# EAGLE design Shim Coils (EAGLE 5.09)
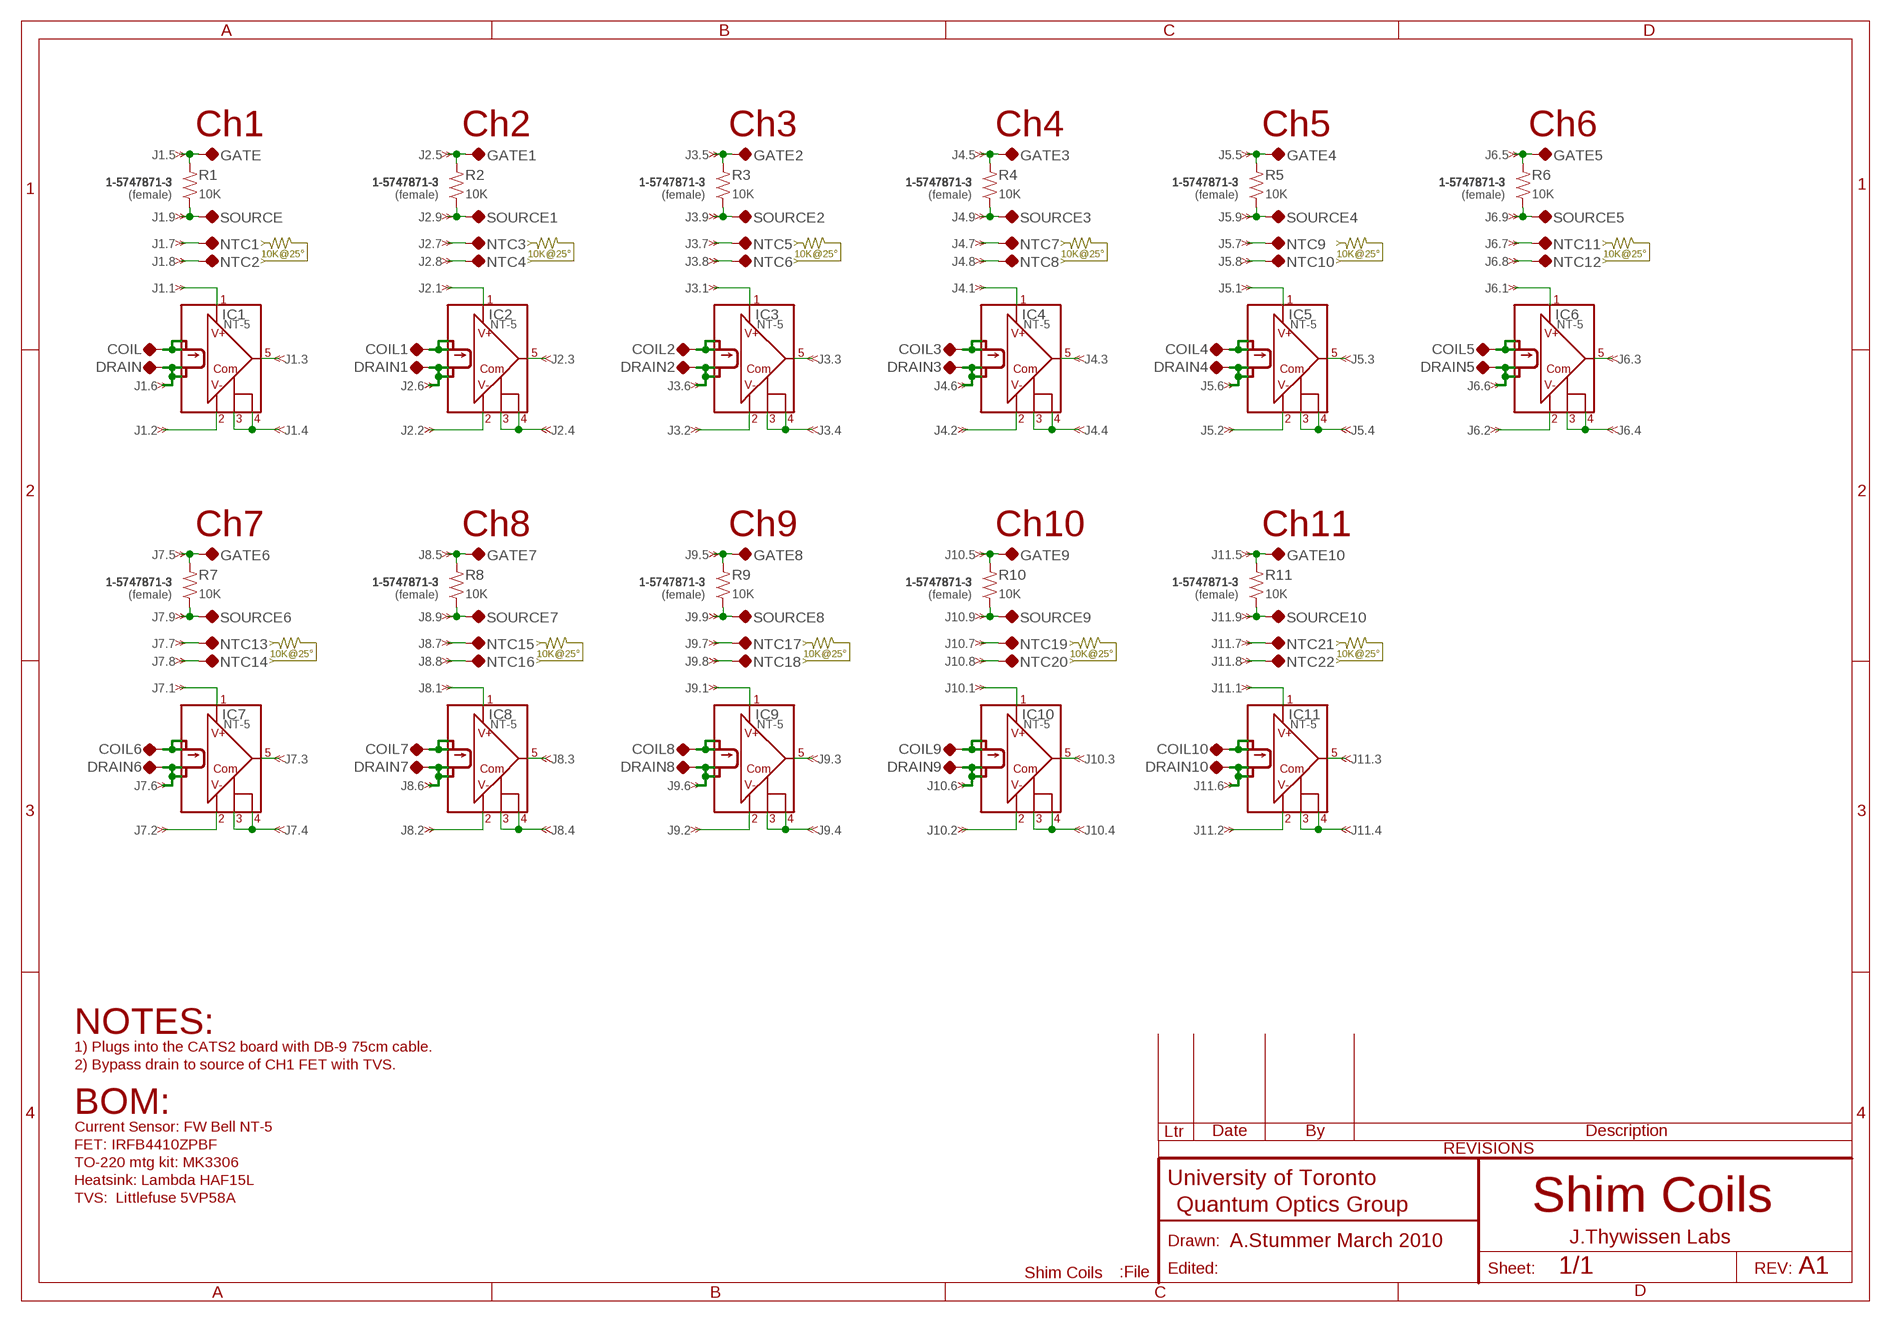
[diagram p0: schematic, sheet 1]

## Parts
COIL  TP-0.052"  [TP-0.052]
COIL1  TP-0.052"  [TP-0.052]
COIL2  TP-0.052"  [TP-0.052]
COIL3  TP-0.052"  [TP-0.052]
COIL4  TP-0.052"  [TP-0.052]
COIL5  TP-0.052"  [TP-0.052]
COIL6  TP-0.052"  [TP-0.052]
COIL7  TP-0.052"  [TP-0.052]
COIL8  TP-0.052"  [TP-0.052]
COIL9  TP-0.052"  [TP-0.052]
COIL10  TP-0.052"  [TP-0.052]
DRAIN  TP-0.052"  [TP-0.052]
DRAIN1  TP-0.052"  [TP-0.052]
DRAIN2  TP-0.052"  [TP-0.052]
DRAIN3  TP-0.052"  [TP-0.052]
DRAIN4  TP-0.052"  [TP-0.052]
DRAIN5  TP-0.052"  [TP-0.052]
DRAIN6  TP-0.052"  [TP-0.052]
DRAIN7  TP-0.052"  [TP-0.052]
DRAIN8  TP-0.052"  [TP-0.052]
DRAIN9  TP-0.052"  [TP-0.052]
DRAIN10  TP-0.052"  [TP-0.052]
GATE  TP-0.052"  [TP-0.052]
GATE1  TP-0.052"  [TP-0.052]
GATE2  TP-0.052"  [TP-0.052]
GATE3  TP-0.052"  [TP-0.052]
GATE4  TP-0.052"  [TP-0.052]
GATE5  TP-0.052"  [TP-0.052]
GATE6  TP-0.052"  [TP-0.052]
GATE7  TP-0.052"  [TP-0.052]
GATE8  TP-0.052"  [TP-0.052]
GATE9  TP-0.052"  [TP-0.052]
GATE10  TP-0.052"  [TP-0.052]
IC1  NT-5  CURRENT_SENSOR:NT-X(F.W.BELL)-NT5/15/25  [CURRENT_SENSOR:NT-5/15/25(F.W.BELL)]
IC2  NT-5  CURRENT_SENSOR:NT-X(F.W.BELL)-NT5/15/25  [CURRENT_SENSOR:NT-5/15/25(F.W.BELL)]
IC3  NT-5  CURRENT_SENSOR:NT-X(F.W.BELL)-NT5/15/25  [CURRENT_SENSOR:NT-5/15/25(F.W.BELL)]
IC4  NT-5  CURRENT_SENSOR:NT-X(F.W.BELL)-NT5/15/25  [CURRENT_SENSOR:NT-5/15/25(F.W.BELL)]
IC5  NT-5  CURRENT_SENSOR:NT-X(F.W.BELL)-NT5/15/25  [CURRENT_SENSOR:NT-5/15/25(F.W.BELL)]
IC6  NT-5  CURRENT_SENSOR:NT-X(F.W.BELL)-NT5/15/25  [CURRENT_SENSOR:NT-5/15/25(F.W.BELL)]
IC7  NT-5  CURRENT_SENSOR:NT-X(F.W.BELL)-NT5/15/25  [CURRENT_SENSOR:NT-5/15/25(F.W.BELL)]
IC8  NT-5  CURRENT_SENSOR:NT-X(F.W.BELL)-NT5/15/25  [CURRENT_SENSOR:NT-5/15/25(F.W.BELL)]
IC9  NT-5  CURRENT_SENSOR:NT-X(F.W.BELL)-NT5/15/25  [CURRENT_SENSOR:NT-5/15/25(F.W.BELL)]
IC10  NT-5  CURRENT_SENSOR:NT-X(F.W.BELL)-NT5/15/25  [CURRENT_SENSOR:NT-5/15/25(F.W.BELL)]
IC11  NT-5  CURRENT_SENSOR:NT-X(F.W.BELL)-NT5/15/25  [CURRENT_SENSOR:NT-5/15/25(F.W.BELL)]
J1  1-5747871-3  CONN-DB9-TYPE2-TYCO_5747150-7_ET_AL  [CONN-DB9-MALE-V2]
J2  1-5747871-3  CONN-DB9-TYPE2-TYCO_5747150-7_ET_AL  [CONN-DB9-MALE-V2]
J3  1-5747871-3  CONN-DB9-TYPE2-TYCO_5747150-7_ET_AL  [CONN-DB9-MALE-V2]
J4  1-5747871-3  CONN-DB9-TYPE2-TYCO_5747150-7_ET_AL  [CONN-DB9-MALE-V2]
J5  1-5747871-3  CONN-DB9-TYPE2-TYCO_5747150-7_ET_AL  [CONN-DB9-MALE-V2]
J6  1-5747871-3  CONN-DB9-TYPE2-TYCO_5747150-7_ET_AL  [CONN-DB9-MALE-V2]
J7  1-5747871-3  CONN-DB9-TYPE2-TYCO_5747150-7_ET_AL  [CONN-DB9-MALE-V2]
J8  1-5747871-3  CONN-DB9-TYPE2-TYCO_5747150-7_ET_AL  [CONN-DB9-MALE-V2]
J9  1-5747871-3  CONN-DB9-TYPE2-TYCO_5747150-7_ET_AL  [CONN-DB9-MALE-V2]
J10  1-5747871-3  CONN-DB9-TYPE2-TYCO_5747150-7_ET_AL  [CONN-DB9-MALE-V2]
J11  1-5747871-3  CONN-DB9-TYPE2-TYCO_5747150-7_ET_AL  [CONN-DB9-MALE-V2]
NTC1  TP-0.052"  [TP-0.052]
NTC2  TP-0.052"  [TP-0.052]
NTC3  TP-0.052"  [TP-0.052]
NTC4  TP-0.052"  [TP-0.052]
NTC5  TP-0.052"  [TP-0.052]
NTC6  TP-0.052"  [TP-0.052]
NTC7  TP-0.052"  [TP-0.052]
NTC8  TP-0.052"  [TP-0.052]
NTC9  TP-0.052"  [TP-0.052]
NTC10  TP-0.052"  [TP-0.052]
NTC11  TP-0.052"  [TP-0.052]
NTC12  TP-0.052"  [TP-0.052]
NTC13  TP-0.052"  [TP-0.052]
NTC14  TP-0.052"  [TP-0.052]
NTC15  TP-0.052"  [TP-0.052]
NTC16  TP-0.052"  [TP-0.052]
NTC17  TP-0.052"  [TP-0.052]
NTC18  TP-0.052"  [TP-0.052]
NTC19  TP-0.052"  [TP-0.052]
NTC20  TP-0.052"  [TP-0.052]
NTC21  TP-0.052"  [TP-0.052]
NTC22  TP-0.052"  [TP-0.052]
R1  10K  R-V-0805  [2012(0805)]
R2  10K  R-V-0805  [2012(0805)]
R3  10K  R-V-0805  [2012(0805)]
R4  10K  R-V-0805  [2012(0805)]
R5  10K  R-V-0805  [2012(0805)]
R6  10K  R-V-0805  [2012(0805)]
R7  10K  R-V-0805  [2012(0805)]
R8  10K  R-V-0805  [2012(0805)]
R9  10K  R-V-0805  [2012(0805)]
R10  10K  R-V-0805  [2012(0805)]
R11  10K  R-V-0805  [2012(0805)]
SOURCE  TP-0.052"  [TP-0.052]
SOURCE1  TP-0.052"  [TP-0.052]
SOURCE2  TP-0.052"  [TP-0.052]
SOURCE3  TP-0.052"  [TP-0.052]
SOURCE4  TP-0.052"  [TP-0.052]
SOURCE5  TP-0.052"  [TP-0.052]
SOURCE6  TP-0.052"  [TP-0.052]
SOURCE7  TP-0.052"  [TP-0.052]
SOURCE8  TP-0.052"  [TP-0.052]
SOURCE9  TP-0.052"  [TP-0.052]
SOURCE10  TP-0.052"  [TP-0.052]

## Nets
N$1: IC1.+V(+VS) J1.5
N$2: IC1.-V(-VS) J1.4
N$3: IC1.OUT J1.3
N$4: IC1.GND1(COM1) IC1.GND2(COM2) J1.2
N$5: GATE.TP J1.1 R1.2
N$6: DRAIN.TP IC1.CURRENT-1 IC1.CURRENT-2 J1.9
N$7: J1.8 NTC1.TP
N$8: J1.7 NTC2.TP
N$9: J1.6 R1.1 SOURCE.TP
N$10: COIL.TP IC1.CURRENT+1 IC1.CURRENT+2
N$11: IC2.+V(+VS) J2.5
N$12: IC2.-V(-VS) J2.4
N$13: IC2.OUT J2.3
N$14: IC2.GND1(COM1) IC2.GND2(COM2) J2.2
N$15: GATE1.TP J2.1 R2.2
N$16: J2.8 NTC3.TP
N$17: J2.7 NTC4.TP
N$18: J2.6 R2.1 SOURCE1.TP
N$19: DRAIN1.TP IC2.CURRENT-1 IC2.CURRENT-2 J2.9
N$20: COIL1.TP IC2.CURRENT+1 IC2.CURRENT+2
N$21: IC3.+V(+VS) J3.5
N$22: IC3.-V(-VS) J3.4
N$23: IC3.OUT J3.3
N$24: IC3.GND1(COM1) IC3.GND2(COM2) J3.2
N$25: GATE2.TP J3.1 R3.2
N$26: J3.8 NTC5.TP
N$27: J3.7 NTC6.TP
N$28: J3.6 R3.1 SOURCE2.TP
N$29: DRAIN2.TP IC3.CURRENT-1 IC3.CURRENT-2 J3.9
N$30: COIL2.TP IC3.CURRENT+1 IC3.CURRENT+2
N$31: IC4.+V(+VS) J4.5
N$32: IC4.-V(-VS) J4.4
N$33: IC4.OUT J4.3
N$34: IC4.GND1(COM1) IC4.GND2(COM2) J4.2
N$35: GATE3.TP J4.1 R4.2
N$36: J4.8 NTC7.TP
N$37: J4.7 NTC8.TP
N$38: J4.6 R4.1 SOURCE3.TP
N$39: DRAIN3.TP IC4.CURRENT-1 IC4.CURRENT-2 J4.9
N$40: COIL3.TP IC4.CURRENT+1 IC4.CURRENT+2
N$41: IC5.+V(+VS) J5.5
N$42: IC5.-V(-VS) J5.4
N$43: IC5.OUT J5.3
N$44: IC5.GND1(COM1) IC5.GND2(COM2) J5.2
N$45: GATE4.TP J5.1 R5.2
N$46: J5.8 NTC9.TP
N$47: J5.7 NTC10.TP
N$48: J5.6 R5.1 SOURCE4.TP
N$49: DRAIN4.TP IC5.CURRENT-1 IC5.CURRENT-2 J5.9
N$50: COIL4.TP IC5.CURRENT+1 IC5.CURRENT+2
N$51: IC6.+V(+VS) J6.5
N$52: IC6.-V(-VS) J6.4
N$53: IC6.OUT J6.3
N$54: IC6.GND1(COM1) IC6.GND2(COM2) J6.2
N$55: GATE5.TP J6.1 R6.2
N$56: J6.8 NTC11.TP
N$57: J6.7 NTC12.TP
N$58: J6.6 R6.1 SOURCE5.TP
N$59: DRAIN5.TP IC6.CURRENT-1 IC6.CURRENT-2 J6.9
N$60: COIL5.TP IC6.CURRENT+1 IC6.CURRENT+2
N$61: IC7.+V(+VS) J7.5
N$62: IC7.-V(-VS) J7.4
N$63: IC7.OUT J7.3
N$64: IC7.GND1(COM1) IC7.GND2(COM2) J7.2
N$65: GATE6.TP J7.1 R7.2
N$66: J7.8 NTC13.TP
N$67: J7.7 NTC14.TP
N$68: J7.6 R7.1 SOURCE6.TP
N$69: DRAIN6.TP IC7.CURRENT-1 IC7.CURRENT-2 J7.9
N$70: COIL6.TP IC7.CURRENT+1 IC7.CURRENT+2
N$71: IC8.+V(+VS) J8.5
N$72: IC8.-V(-VS) J8.4
N$73: IC8.OUT J8.3
N$74: IC8.GND1(COM1) IC8.GND2(COM2) J8.2
N$75: GATE7.TP J8.1 R8.2
N$76: J8.8 NTC15.TP
N$77: J8.7 NTC16.TP
N$78: J8.6 R8.1 SOURCE7.TP
N$79: DRAIN7.TP IC8.CURRENT-1 IC8.CURRENT-2 J8.9
N$80: COIL7.TP IC8.CURRENT+1 IC8.CURRENT+2
N$81: IC9.+V(+VS) J9.5
N$82: IC9.-V(-VS) J9.4
N$83: IC9.OUT J9.3
N$84: IC9.GND1(COM1) IC9.GND2(COM2) J9.2
N$85: GATE8.TP J9.1 R9.2
N$86: J9.8 NTC17.TP
N$87: J9.7 NTC18.TP
N$88: J9.6 R9.1 SOURCE8.TP
N$89: DRAIN8.TP IC9.CURRENT-1 IC9.CURRENT-2 J9.9
N$90: COIL8.TP IC9.CURRENT+1 IC9.CURRENT+2
N$91: IC10.+V(+VS) J10.5
N$92: IC10.-V(-VS) J10.4
N$93: IC10.OUT J10.3
N$94: IC10.GND1(COM1) IC10.GND2(COM2) J10.2
N$95: GATE9.TP J10.1 R10.2
N$96: J10.8 NTC19.TP
N$97: J10.7 NTC20.TP
N$98: J10.6 R10.1 SOURCE9.TP
N$99: DRAIN9.TP IC10.CURRENT-1 IC10.CURRENT-2 J10.9
N$100: COIL9.TP IC10.CURRENT+1 IC10.CURRENT+2
N$101: IC11.+V(+VS) J11.5
N$102: IC11.-V(-VS) J11.4
N$103: IC11.OUT J11.3
N$104: IC11.GND1(COM1) IC11.GND2(COM2) J11.2
N$105: GATE10.TP J11.1 R11.2
N$106: J11.8 NTC21.TP
N$107: J11.7 NTC22.TP
N$108: J11.6 R11.1 SOURCE10.TP
N$109: DRAIN10.TP IC11.CURRENT-1 IC11.CURRENT-2 J11.9
N$110: COIL10.TP IC11.CURRENT+1 IC11.CURRENT+2

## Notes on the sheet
- Ch1 | Ch2 | Ch3 | Ch4 | Ch5 | Ch6
- (female) | (female) | (female) | (female) | (female) | (female)
- 10K@25° | 10K@25° | 10K@25° | 10K@25° | 10K@25° | 10K@25°
- Ch7 | Ch8 | Ch9 | Ch10 | Ch11
- (female) | (female) | (female) | (female) | (female)
- 10K@25° | 10K@25° | 10K@25° | 10K@25° | 10K@25°
- NOTES:
- 1) Plugs into the CATS2 board with DB-9 75cm cable.
- 2) Bypass drain to source of CH1 FET with TVS.
- BOM:
- Current Sensor: FW Bell NT-5
- FET: IRFB4410ZPBF
- TO-220 mtg kit: MK3306
- Heatsink: Lambda HAF15L
- TVS:  Littlefuse 5VP58A
- Shim Coils
- A.Stummer March 2010 | J.Thywissen Labs
- A1

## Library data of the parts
COIL COIL1-COIL10 DRAIN DRAIN1-DRAIN10 GATE GATE1-GATE10 NTC1-NTC22 SOURCE SOURCE1-SOURCE10 = QuantumOptics:TP: Testpoint, either SMT pad, small hole or loop style TP such as Keystone 5002K (0.042").
IC1-IC11 = QuantumOptics:CURRENT_SENSOR:NT-X(F.W.BELL): Current Sensor, NT-5 -15 -25, F.W.Bell, 5/15/25A, bipolar, ±15V supply. http://www.sypris.com/filemanager/library/NT-Datasheet.pdf
J1-J11 = QuantumOptics:CONN-DB9-TYPE2: Connector, DB9, board mount, e.g. Tyco 1-5747150-4.
R1-R11 = QuantumOptics:R-V-*: Resistor, SMT & Through-Hole, vertical symbol

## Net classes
0 default: width 0.2 mm, drill 0.508 mm
1 Power: width 1.27 mm, drill 0.711 mm

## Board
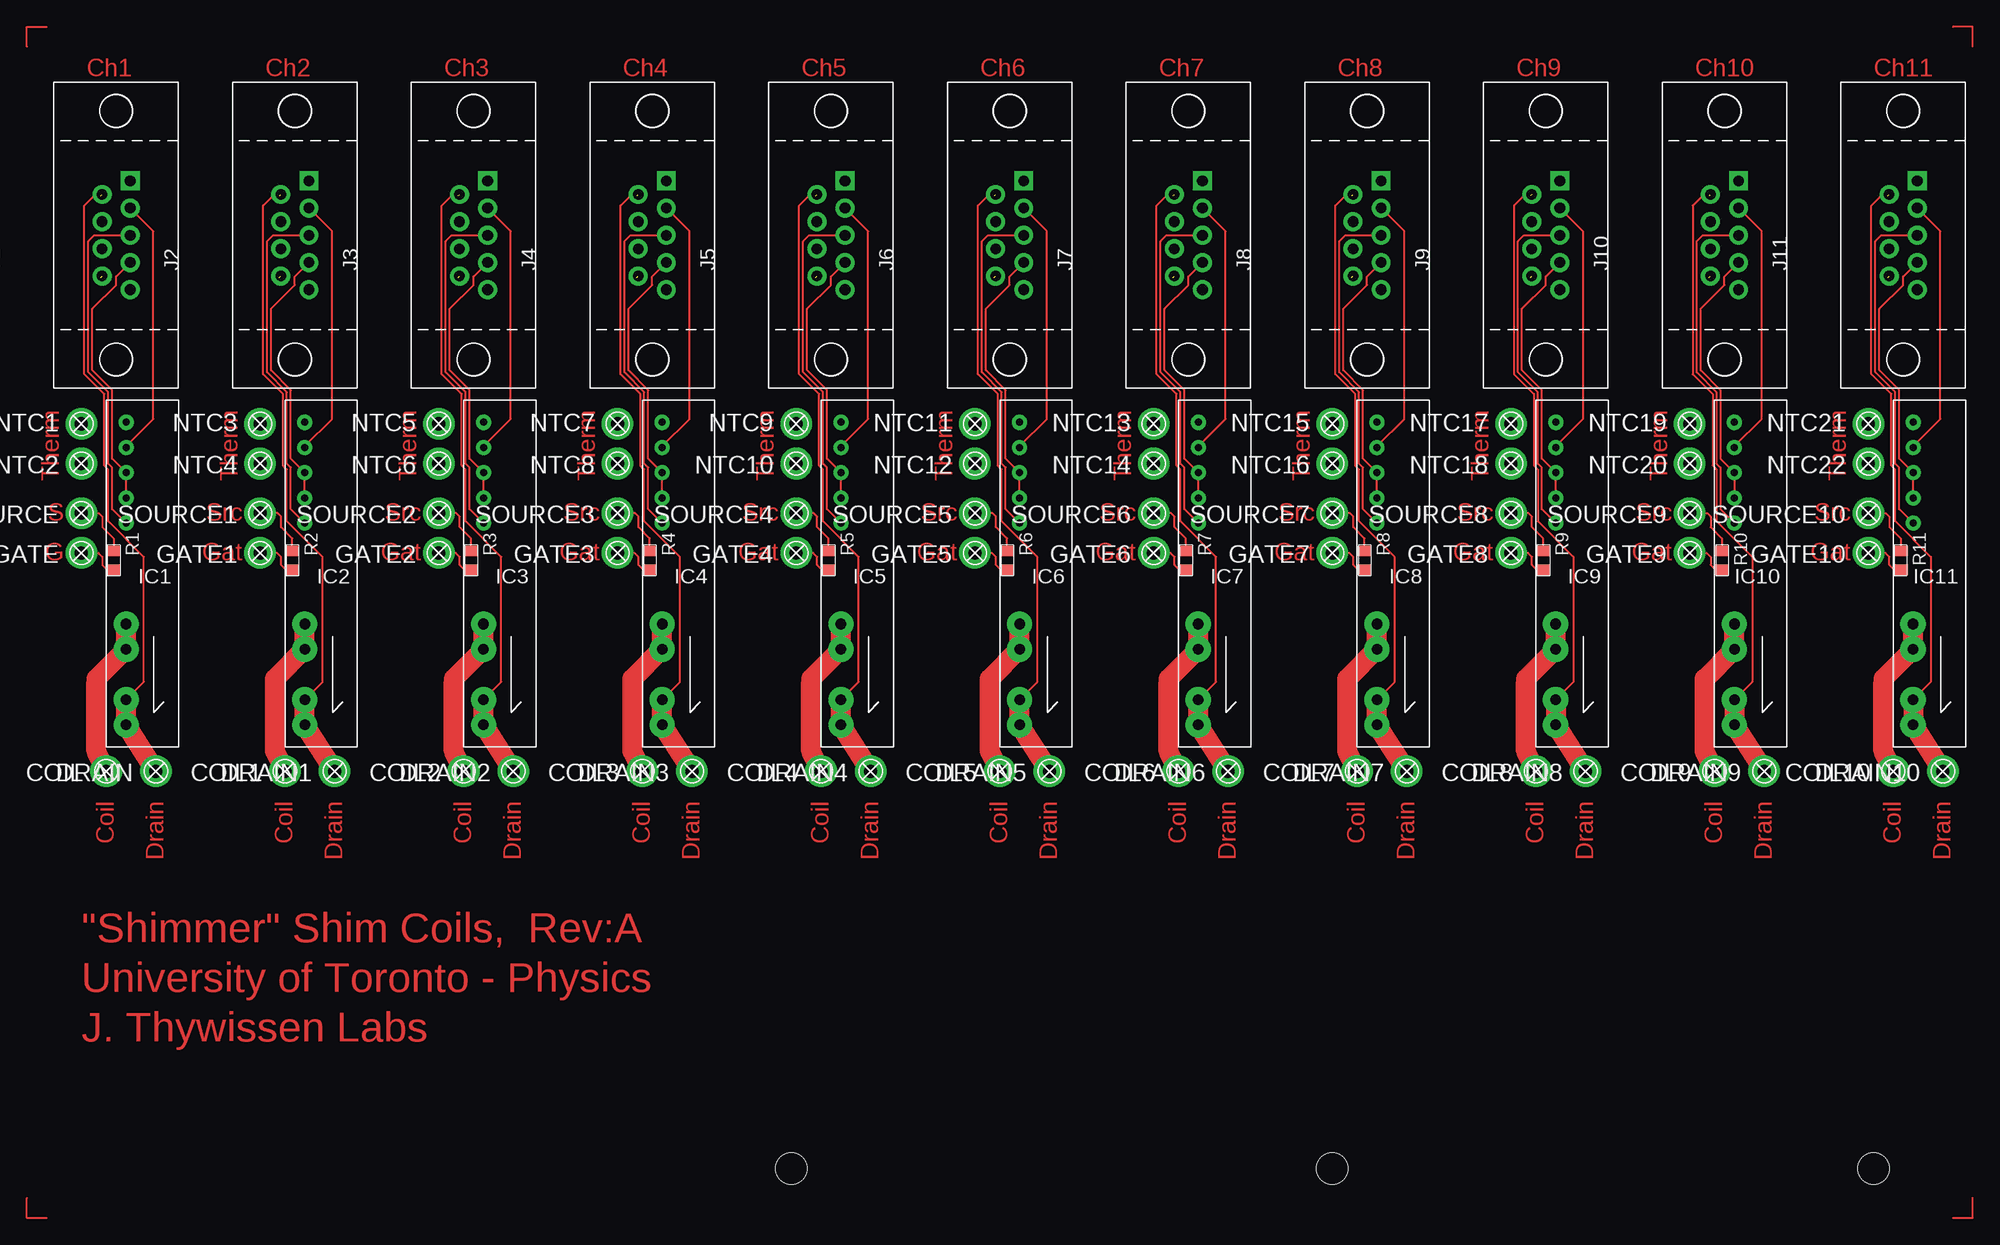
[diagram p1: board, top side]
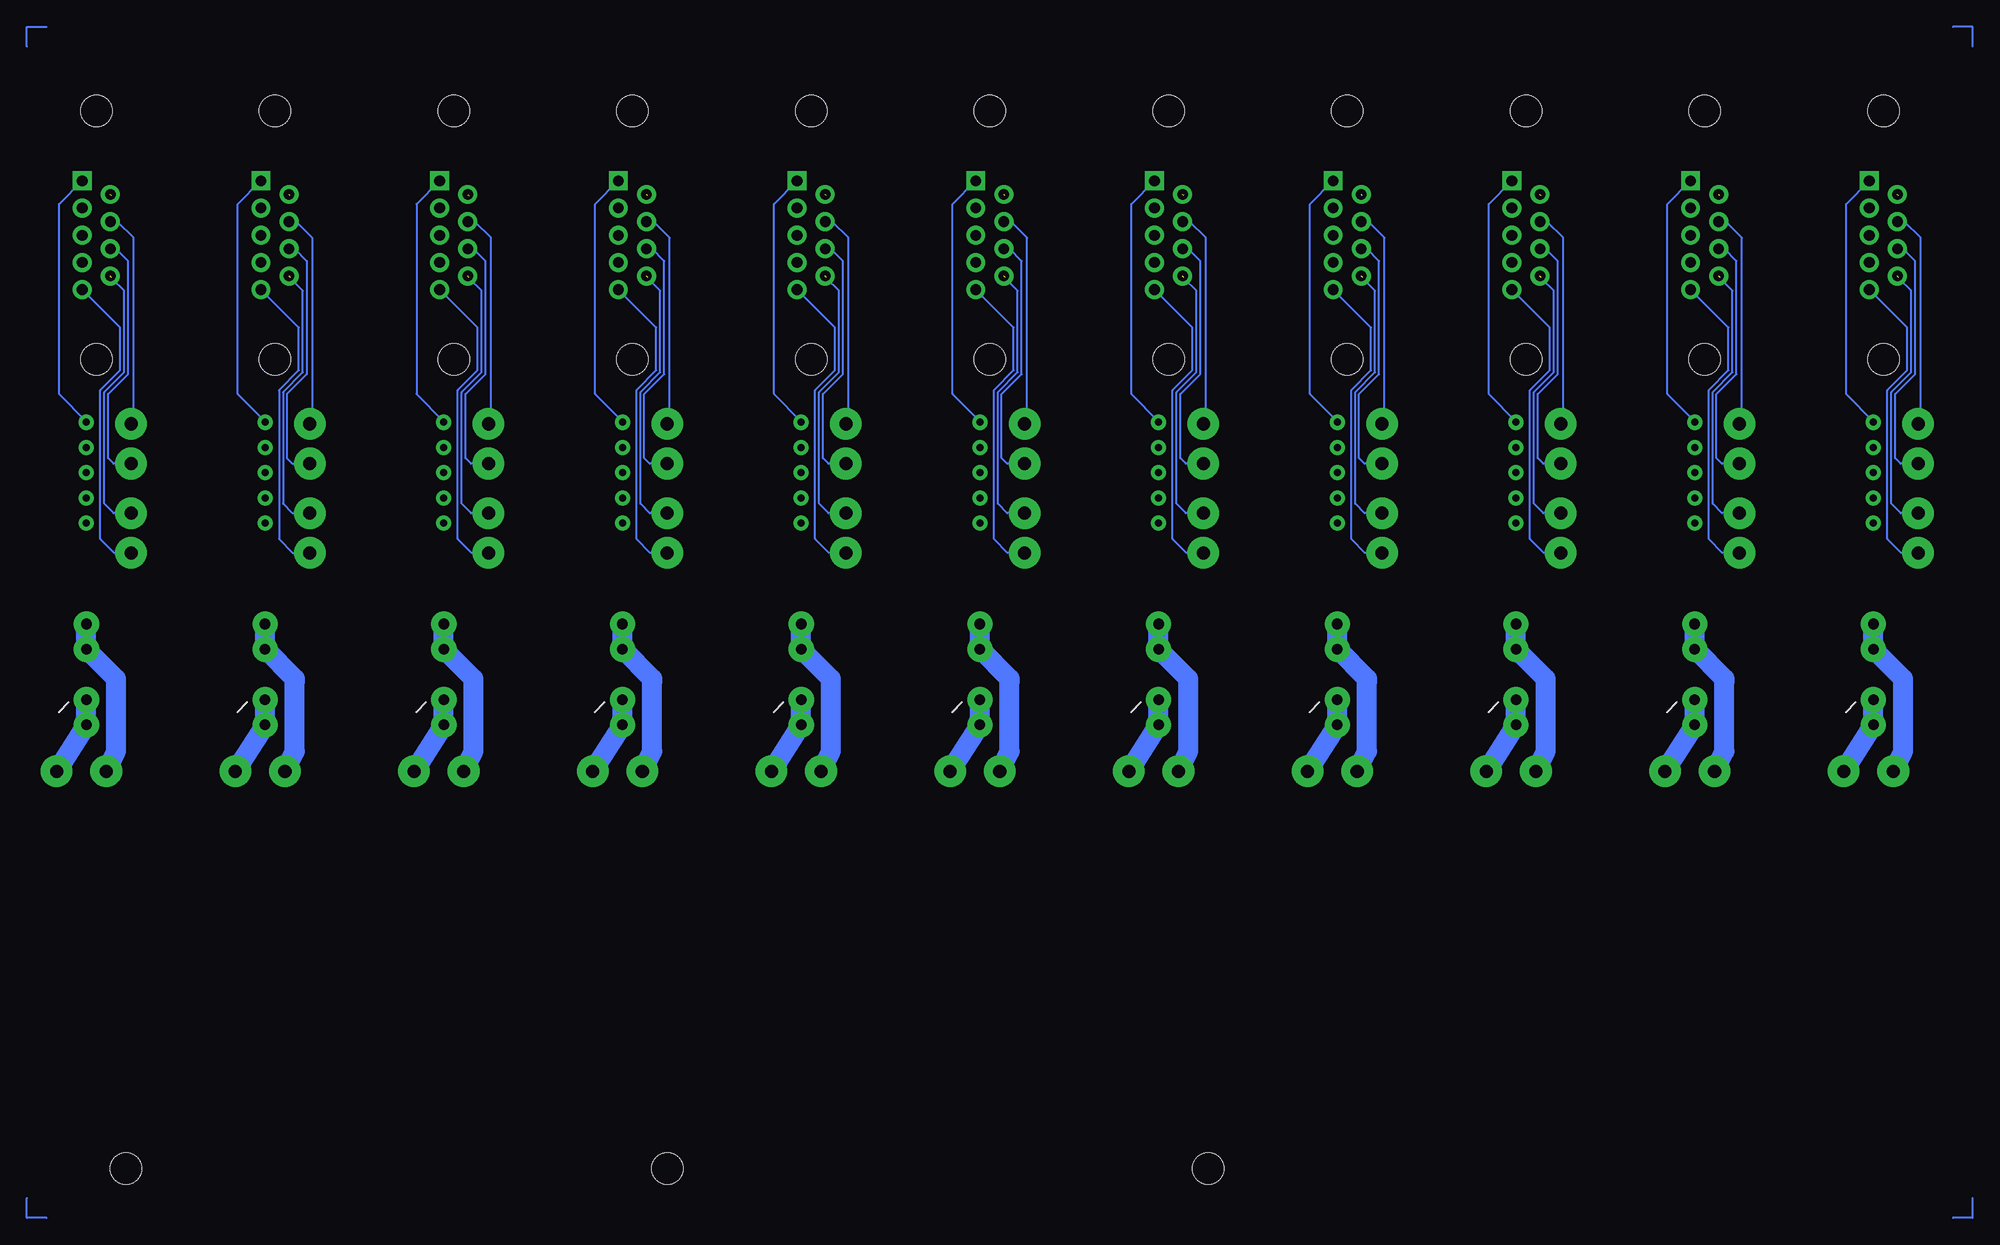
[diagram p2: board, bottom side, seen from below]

No outline drawn. Coordinates in mm, seen from the top.
Copper layers (1+16): Top 0.035mm / dielectric 1.5mm / Bottom 0.035mm
Design rules "DRC standard check": minimum track width 7mil, minimum drill 20mil, track to track 7mil, track to pad 7mil, pad to pad 7mil, via to via 7mil, smd to smd 0mil, copper to edge 25mil, drill to drill 8mil, minimum pad ring 10mil, minimum via ring 8mil, stop-mask expansion 4mil, vias tented up to drill 0mil, thermal gap 10mil
Holes 3.17 mm at 77,5 186,5 131.5,5

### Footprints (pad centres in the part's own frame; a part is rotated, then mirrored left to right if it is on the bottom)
TP-0.052 = drill 1.321 pad 3.175 round: TP 0,0
CURRENT_SENSOR:NT-5/15/25(F.W.BELL) = drill 0.711 pad 1.524 round: +V 0,-10.16; -V 0,-7.62; GND1 0,-5.08; GND2 0,-2.54; OUT 0,0 | drill 1.067 pad 2.54 round: CURRENT+1 0,10.16; CURRENT+2 0,12.7; CURRENT-1 0,20.32; CURRENT-2 0,17.78
CONN-DB9-MALE-V2 = drill 1.067 pad 1.905 round: 1 -5.48,-1.42; 2 -2.74,-1.42; 3 0,-1.42; 4 2.74,-1.42; 6 -4.11,1.42; 7 -1.37,1.42; 8 1.37,1.42; 9 4.11,1.42 | drill 1.067 pad 1.905 square: 5 5.48,-1.42 | hole 3.175: -12.5,0; 12.5,0
2012(0805) = smd 1.016 x 1.397: 1 -0.953,0; 2 0.953,0

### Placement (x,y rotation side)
COIL  8,45 180 top
COIL1  26,45 180 top
COIL2  44,45 180 top
COIL3  62,45 180 top
COIL4  80,45 180 top
COIL5  98,45 180 top
COIL6  116,45 180 top
COIL7  134,45 180 top
COIL8  152,45 180 top
COIL9  170,45 180 top
COIL10  188,45 180 top
DRAIN  13,45 180 top
DRAIN1  31,45 180 top
DRAIN2  49,45 180 top
DRAIN3  67,45 180 top
DRAIN4  85,45 180 top
DRAIN5  103,45 180 top
DRAIN6  121,45 180 top
DRAIN7  139,45 180 top
DRAIN8  157,45 180 top
DRAIN9  175,45 180 top
DRAIN10  193,45 180 top
GATE  5.5,67 180 top
GATE1  23.5,67 180 top
GATE2  41.5,67 180 top
GATE3  59.5,67 180 top
GATE4  77.5,67 180 top
GATE5  95.5,67 180 top
GATE6  113.5,67 180 top
GATE7  131.5,67 180 top
GATE8  149.5,67 180 top
GATE9  167.5,67 180 top
GATE10  185.5,67 180 top
IC1  10,70 180 top
IC2  28,70 180 top
IC3  46,70 180 top
IC4  64,70 180 top
IC5  82,70 180 top
IC6  100,70 180 top
IC7  118,70 180 top
IC8  136,70 180 top
IC9  154,70 180 top
IC10  172,70 180 top
IC11  190,70 180 top
J1  9,99 90 top
J2  27,99 90 top
J3  45,99 90 top
J4  63,99 90 top
J5  81,99 90 top
J6  99,99 90 top
J7  117,99 90 top
J8  135,99 90 top
J9  153,99 90 top
J10  171,99 90 top
J11  189,99 90 top
NTC1  5.5,80 270 top
NTC2  5.5,76 180 top
NTC3  23.5,80 270 top
NTC4  23.5,76 180 top
NTC5  41.5,80 270 top
NTC6  41.5,76 180 top
NTC7  59.5,80 270 top
NTC8  59.5,76 180 top
NTC9  77.5,80 270 top
NTC10  77.5,76 180 top
NTC11  95.5,80 270 top
NTC12  95.5,76 180 top
NTC13  113.5,80 270 top
NTC14  113.5,76 180 top
NTC15  131.5,80 270 top
NTC16  131.5,76 180 top
NTC17  149.5,80 270 top
NTC18  149.5,76 180 top
NTC19  167.5,80 270 top
NTC20  167.5,76 180 top
NTC21  185.5,80 270 top
NTC22  185.5,76 180 top
R1  8.75,66.25 270 top
R2  26.75,66.25 270 top
R3  44.75,66.25 270 top
R4  62.75,66.25 270 top
R5  80.75,66.25 270 top
R6  98.75,66.25 270 top
R7  116.75,66.25 270 top
R8  134.75,66.25 270 top
R9  152.75,66.25 270 top
R10  170.75,66.25 270 top
R11  188.75,66.25 270 top
SOURCE  5.5,71 180 top
SOURCE1  23.5,71 180 top
SOURCE2  41.5,71 180 top
SOURCE3  59.5,71 180 top
SOURCE4  77.5,71 180 top
SOURCE5  95.5,71 180 top
SOURCE6  113.5,71 180 top
SOURCE7  131.5,71 180 top
SOURCE8  149.5,71 180 top
SOURCE9  167.5,71 180 top
SOURCE10  185.5,71 180 top
U$1  [TITLEBLOCK_PCB]  0,-7 0 top

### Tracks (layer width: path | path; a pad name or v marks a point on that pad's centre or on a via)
N$1
  Bottom 0.2: IC1.+V 10,80.25 12.75,83 12.75,102.15 J1.5
N$2
  Top 0.2: IC1.-V 10,77.75 12.75,80.5 12.75,99.41 J1.4
N$3
  Top 0.2: J1.3 6.8,99 6.2,98.4 6.2,85.2 8.2,83.2 8.2,76 8.6,75.6 8.6,71.4 IC1.OUT
N$4
  Top 0.2: IC1.GND2 IC1.GND1 8.6,76.48 8.6,83.4 6.6,85.4 6.6,91.6 9,94 9,94.84 J1.2
N$5
  Top 0.2: R1.2 8.1,65.3 7.6,65.8 7.6,66.6 7.2,67 GATE.TP
  Bottom 0.2: J1.1 6.6,89.7 6.6,85.4 8.6,83.4 8.6,68.4 7.2,67 GATE.TP
N$6  (1 unrouted)
  Top 0.2: 10,52.25 IC1.CURRENT-2 11.8,54.02 11.8,66.6 8.2,70.2 8.2,75.4 7.8,75.8 7.8,83 5.8,85 5.8,102 6.8,103 7.47,103
  Top 1.27: IC1.CURRENT-2 10,52
  Top 2: IC1.CURRENT-2 IC1.CURRENT-1 DRAIN.TP
  Bottom 1.27: IC1.CURRENT-2 10,52
  Bottom 2: 10,52 IC1.CURRENT-1 DRAIN.TP
N$7
  Bottom 0.2: J1.8 6.87,100.37 5.25,98.75 5.25,80.25 NTC1.TP
N$8
  Bottom 0.2: J1.7 7.03,97.63 5.8,96.4 5.8,85 7.8,83 7.8,76.55 7.25,76 NTC2.TP
N$9  (1 unrouted)
  Top 0.2: R1.1 8.75,68.45 7.6,69.6 7.6,70.65 7.25,71 SOURCE.TP
  Bottom 0.2: 7.44,94.75 7.44,94.64 6.2,93.4 6.2,85.2 8.2,83.2 8.2,71.95 7.25,71 SOURCE.TP
N$10
  Top 0.2: 7,54 7,54.3
  Top 1.27: IC1.CURRENT+1 10,60
  Top 2: 7,54 7,47 COIL.TP | IC1.CURRENT+1 IC1.CURRENT+2 7,54.3
  Bottom 2: COIL.TP 7,47 7,54 | IC1.CURRENT+1 IC1.CURRENT+2 7,54.3
N$11
  Bottom 0.2: IC2.+V 28,80.25 30.75,83 30.75,102.15 J2.5
N$12
  Top 0.2: IC2.-V 28,77.75 30.75,80.5 30.75,99.41 J2.4
N$13
  Top 0.2: J2.3 24.8,99 24.2,98.4 24.2,85.2 26.2,83.2 26.2,76 26.6,75.6 26.6,71.4 IC2.OUT
N$14
  Top 0.2: IC2.GND2 IC2.GND1 26.6,76.48 26.6,83.4 24.6,85.4 24.6,91.6 27,94 27,94.84 J2.2
N$15
  Top 0.2: R2.2 26.1,65.3 25.6,65.8 25.6,66.6 25.2,67 GATE1.TP
  Bottom 0.2: J2.1 24.6,89.7 24.6,85.4 26.6,83.4 26.6,68.4 25.2,67 GATE1.TP
N$16
  Bottom 0.2: J2.8 24.87,100.37 23.25,98.75 23.25,80.25 NTC3.TP
N$17
  Bottom 0.2: J2.7 25.03,97.63 23.8,96.4 23.8,85 25.8,83 25.8,76.55 25.25,76 NTC4.TP
N$18  (1 unrouted)
  Top 0.2: R2.1 26.75,68.45 25.6,69.6 25.6,70.65 25.25,71 SOURCE1.TP
  Bottom 0.2: 25.44,94.75 25.44,94.64 24.2,93.4 24.2,85.2 26.2,83.2 26.2,71.95 25.25,71 SOURCE1.TP
N$19  (1 unrouted)
  Top 0.2: 28,52.25 IC2.CURRENT-2 29.8,54.02 29.8,66.6 26.2,70.2 26.2,75.4 25.8,75.8 25.8,83 23.8,85 23.8,102 24.8,103 25.47,103
  Top 1.27: IC2.CURRENT-2 28,52
  Top 2: IC2.CURRENT-2 IC2.CURRENT-1 DRAIN1.TP
  Bottom 1.27: IC2.CURRENT-2 28,52
  Bottom 2: 28,52 IC2.CURRENT-1 DRAIN1.TP
N$20
  Top 1.27: IC2.CURRENT+1 28,60
  Top 2: 25,54 25,47 COIL1.TP | IC2.CURRENT+1 IC2.CURRENT+2 25,54.3
  Bottom 0.2: 25,54 25,54.3
  Bottom 2: COIL1.TP 25,47 25,54 | IC2.CURRENT+1 IC2.CURRENT+2 25,54.3
N$21
  Bottom 0.2: IC3.+V 46,80.25 48.75,83 48.75,102.15 J3.5
N$22
  Top 0.2: IC3.-V 46,77.75 48.75,80.5 48.75,99.41 J3.4
N$23
  Top 0.2: J3.3 42.8,99 42.2,98.4 42.2,85.2 44.2,83.2 44.2,76 44.6,75.6 44.6,71.4 IC3.OUT
N$24
  Top 0.2: IC3.GND2 IC3.GND1 44.6,76.48 44.6,83.4 42.6,85.4 42.6,91.6 45,94 45,94.84 J3.2
N$25
  Top 0.2: R3.2 44.1,65.3 43.6,65.8 43.6,66.6 43.2,67 GATE2.TP
  Bottom 0.2: J3.1 42.6,89.7 42.6,85.4 44.6,83.4 44.6,68.4 43.2,67 GATE2.TP
N$26
  Bottom 0.2: J3.8 42.87,100.37 41.25,98.75 41.25,80.25 NTC5.TP
N$27
  Bottom 0.2: J3.7 43.03,97.63 41.8,96.4 41.8,85 43.8,83 43.8,76.55 43.25,76 NTC6.TP
N$28  (1 unrouted)
  Top 0.2: R3.1 44.75,68.45 43.6,69.6 43.6,70.65 43.25,71 SOURCE2.TP
  Bottom 0.2: 43.44,94.75 43.44,94.64 42.2,93.4 42.2,85.2 44.2,83.2 44.2,71.95 43.25,71 SOURCE2.TP
N$29  (1 unrouted)
  Top 0.2: 46,52.25 IC3.CURRENT-2 47.8,54.02 47.8,66.6 44.2,70.2 44.2,75.4 43.8,75.8 43.8,83 41.8,85 41.8,102 42.8,103 43.47,103
  Top 1.27: IC3.CURRENT-2 46,52
  Top 2: IC3.CURRENT-2 IC3.CURRENT-1 DRAIN2.TP
  Bottom 1.27: IC3.CURRENT-2 46,52
  Bottom 2: 46,52 IC3.CURRENT-1 DRAIN2.TP
N$30
  Top 1.27: IC3.CURRENT+1 46,60
  Top 2: 43,54 43,47 COIL2.TP | IC3.CURRENT+1 IC3.CURRENT+2 43,54.3
  Bottom 0.2: 43,54 43,54.3
  Bottom 2: COIL2.TP 43,47 43,54 | IC3.CURRENT+1 IC3.CURRENT+2 43,54.3
N$31
  Bottom 0.2: IC4.+V 64,80.25 66.75,83 66.75,102.15 J4.5
N$32
  Top 0.2: IC4.-V 64,77.75 66.75,80.5 66.75,99.41 J4.4
N$33
  Top 0.2: J4.3 60.8,99 60.2,98.4 60.2,85.2 62.2,83.2 62.2,76 62.6,75.6 62.6,71.4 IC4.OUT
N$34
  Top 0.2: IC4.GND2 IC4.GND1 62.6,76.48 62.6,83.4 60.6,85.4 60.6,91.6 63,94 63,94.84 J4.2
N$35
  Top 0.2: R4.2 62.1,65.3 61.6,65.8 61.6,66.6 61.2,67 GATE3.TP
  Bottom 0.2: J4.1 60.6,89.7 60.6,85.4 62.6,83.4 62.6,68.4 61.2,67 GATE3.TP
N$36
  Bottom 0.2: J4.8 60.87,100.37 59.25,98.75 59.25,80.25 NTC7.TP
N$37
  Bottom 0.2: J4.7 61.03,97.63 59.8,96.4 59.8,85 61.8,83 61.8,76.55 61.25,76 NTC8.TP
N$38  (1 unrouted)
  Top 0.2: R4.1 62.75,68.45 61.6,69.6 61.6,70.65 61.25,71 SOURCE3.TP
  Bottom 0.2: 61.44,94.75 61.44,94.64 60.2,93.4 60.2,85.2 62.2,83.2 62.2,71.95 61.25,71 SOURCE3.TP
N$39  (1 unrouted)
  Top 0.2: 64,52.25 IC4.CURRENT-2 65.8,54.02 65.8,66.6 62.2,70.2 62.2,75.4 61.8,75.8 61.8,83 59.8,85 59.8,102 60.8,103 61.47,103
  Top 1.27: IC4.CURRENT-2 64,52
  Top 2: IC4.CURRENT-2 IC4.CURRENT-1 DRAIN3.TP
  Bottom 1.27: IC4.CURRENT-2 64,52
  Bottom 2: 64,52 IC4.CURRENT-1 DRAIN3.TP
N$40
  Top 1.27: IC4.CURRENT+1 64,60
  Top 2: 61,54 61,47 COIL3.TP | IC4.CURRENT+1 IC4.CURRENT+2 61,54.3
  Bottom 0.2: 61,54 61,54.3
  Bottom 2: COIL3.TP 61,47 61,54 | IC4.CURRENT+1 IC4.CURRENT+2 61,54.3
N$41
  Bottom 0.2: IC5.+V 82,80.25 84.75,83 84.75,102.15 J5.5
N$42
  Top 0.2: IC5.-V 82,77.75 84.75,80.5 84.75,99.41 J5.4
N$43
  Top 0.2: J5.3 78.8,99 78.2,98.4 78.2,85.2 80.2,83.2 80.2,76 80.6,75.6 80.6,71.4 IC5.OUT
N$44
  Top 0.2: IC5.GND2 IC5.GND1 80.6,76.48 80.6,83.4 78.6,85.4 78.6,91.6 81,94 81,94.84 J5.2
N$45
  Top 0.2: R5.2 80.1,65.3 79.6,65.8 79.6,66.6 79.2,67 GATE4.TP
  Bottom 0.2: J5.1 78.6,89.7 78.6,85.4 80.6,83.4 80.6,68.4 79.2,67 GATE4.TP
N$46
  Bottom 0.2: J5.8 78.87,100.37 77.25,98.75 77.25,80.25 NTC9.TP
N$47
  Bottom 0.2: J5.7 79.03,97.63 77.8,96.4 77.8,85 79.8,83 79.8,76.55 79.25,76 NTC10.TP
N$48  (1 unrouted)
  Top 0.2: R5.1 80.75,68.45 79.6,69.6 79.6,70.65 79.25,71 SOURCE4.TP
  Bottom 0.2: 79.44,94.75 79.44,94.64 78.2,93.4 78.2,85.2 80.2,83.2 80.2,71.95 79.25,71 SOURCE4.TP
N$49  (1 unrouted)
  Top 0.2: 82,52.25 IC5.CURRENT-2 83.8,54.02 83.8,66.6 80.2,70.2 80.2,75.4 79.8,75.8 79.8,83 77.8,85 77.8,102 78.8,103 79.47,103
  Top 1.27: IC5.CURRENT-2 82,52
  Top 2: IC5.CURRENT-2 IC5.CURRENT-1 DRAIN4.TP
  Bottom 1.27: IC5.CURRENT-2 82,52
  Bottom 2: 82,52 IC5.CURRENT-1 DRAIN4.TP
N$50
  Top 0.2: 79,54 79,54.3
  Top 1.27: IC5.CURRENT+1 82,60
  Top 2: COIL4.TP 79,47 79,54 | IC5.CURRENT+1 IC5.CURRENT+2 79,54.3
  Bottom 2: COIL4.TP 79,47 79,54 | IC5.CURRENT+1 IC5.CURRENT+2 79,54.3
N$51
  Bottom 0.2: IC6.+V 100,80.25 102.75,83 102.75,102.15 J6.5
N$52
  Top 0.2: IC6.-V 100,77.75 102.75,80.5 102.75,99.41 J6.4
N$53
  Top 0.2: J6.3 96.8,99 96.2,98.4 96.2,85.2 98.2,83.2 98.2,76 98.6,75.6 98.6,71.4 IC6.OUT
N$54
  Top 0.2: IC6.GND2 IC6.GND1 98.6,76.48 98.6,83.4 96.6,85.4 96.6,91.6 99,94 99,94.84 J6.2
N$55
  Top 0.2: R6.2 98.1,65.3 97.6,65.8 97.6,66.6 97.2,67 GATE5.TP
  Bottom 0.2: J6.1 96.6,89.7 96.6,85.4 98.6,83.4 98.6,68.4 97.2,67 GATE5.TP
N$56
  Bottom 0.2: J6.8 96.87,100.37 95.25,98.75 95.25,80.25 NTC11.TP
N$57
  Bottom 0.2: J6.7 97.03,97.63 95.8,96.4 95.8,85 97.8,83 97.8,76.55 97.25,76 NTC12.TP
N$58  (1 unrouted)
  Top 0.2: R6.1 98.75,68.45 97.6,69.6 97.6,70.65 97.25,71 SOURCE5.TP
  Bottom 0.2: 97.44,94.75 97.44,94.64 96.2,93.4 96.2,85.2 98.2,83.2 98.2,71.95 97.25,71 SOURCE5.TP
N$59  (1 unrouted)
  Top 0.2: 100,52.25 IC6.CURRENT-2 101.8,54.02 101.8,66.6 98.2,70.2 98.2,75.4 97.8,75.8 97.8,83 95.8,85 95.8,102 96.8,103 97.47,103
  Top 1.27: IC6.CURRENT-2 100,52
  Top 2: IC6.CURRENT-2 IC6.CURRENT-1 DRAIN5.TP
  Bottom 1.27: IC6.CURRENT-2 100,52
  Bottom 2: 100,52 IC6.CURRENT-1 DRAIN5.TP
N$60
  Top 1.27: IC6.CURRENT+1 100,60
  Top 2: COIL5.TP 97,47 97,54 | IC6.CURRENT+1 IC6.CURRENT+2 97,54.3
  Bottom 0.2: 97,54 97,54.3
  Bottom 2: COIL5.TP 97,47 97,54 | IC6.CURRENT+1 IC6.CURRENT+2 97,54.3
N$61
  Bottom 0.2: IC7.+V 118,80.25 120.75,83 120.75,102.15 J7.5
N$62
  Top 0.2: IC7.-V 118,77.75 120.75,80.5 120.75,99.41 J7.4
N$63
  Top 0.2: J7.3 114.8,99 114.2,98.4 114.2,85.2 116.2,83.2 116.2,76 116.6,75.6 116.6,71.4 IC7.OUT
N$64
  Top 0.2: IC7.GND2 IC7.GND1 116.6,76.48 116.6,83.4 114.6,85.4 114.6,91.6 117,94 117,94.84 J7.2
N$65
  Top 0.2: R7.2 116.1,65.3 115.6,65.8 115.6,66.6 115.2,67 GATE6.TP
  Bottom 0.2: J7.1 114.6,89.7 114.6,85.4 116.6,83.4 116.6,68.4 115.2,67 GATE6.TP
N$66
  Bottom 0.2: J7.8 114.87,100.37 113.25,98.75 113.25,80.25 NTC13.TP
N$67
  Bottom 0.2: J7.7 115.03,97.63 113.8,96.4 113.8,85 115.8,83 115.8,76.55 115.25,76 NTC14.TP
N$68  (1 unrouted)
  Top 0.2: R7.1 116.75,68.45 115.6,69.6 115.6,70.65 115.25,71 SOURCE6.TP
  Bottom 0.2: 115.44,94.75 115.44,94.64 114.2,93.4 114.2,85.2 116.2,83.2 116.2,71.95 115.25,71 SOURCE6.TP
N$69  (1 unrouted)
  Top 0.2: 118,52.25 IC7.CURRENT-2 119.8,54.02 119.8,66.6 116.2,70.2 116.2,75.4 115.8,75.8 115.8,83 113.8,85 113.8,102 114.8,103 115.47,103
  Top 1.27: IC7.CURRENT-2 118,52
  Top 2: IC7.CURRENT-2 IC7.CURRENT-1 DRAIN6.TP
  Bottom 1.27: IC7.CURRENT-2 118,52
  Bottom 2: 118,52 IC7.CURRENT-1 DRAIN6.TP
N$70
  Top 1.27: IC7.CURRENT+1 118,60
  Top 2: COIL6.TP 115,47 115,54 | IC7.CURRENT+1 IC7.CURRENT+2 115,54.3
  Bottom 0.2: 115,54 115,54.3
  Bottom 2: COIL6.TP 115,47 115,54 | IC7.CURRENT+1 IC7.CURRENT+2 115,54.3
N$71
  Bottom 0.2: IC8.+V 136,80.25 138.75,83 138.75,102.15 J8.5
N$72
  Top 0.2: IC8.-V 136,77.75 138.75,80.5 138.75,99.41 J8.4
N$73
  Top 0.2: J8.3 132.8,99 132.2,98.4 132.2,85.2 134.2,83.2 134.2,76 134.6,75.6 134.6,71.4 IC8.OUT
N$74
  Top 0.2: IC8.GND2 IC8.GND1 134.6,76.48 134.6,83.4 132.6,85.4 132.6,91.6 135,94 135,94.84 J8.2
N$75
  Top 0.2: R8.2 134.1,65.3 133.6,65.8 133.6,66.6 133.2,67 GATE7.TP
  Bottom 0.2: J8.1 132.6,89.7 132.6,85.4 134.6,83.4 134.6,68.4 133.2,67 GATE7.TP
N$76
  Bottom 0.2: J8.8 132.87,100.37 131.25,98.75 131.25,80.25 NTC15.TP
N$77
  Bottom 0.2: J8.7 133.03,97.63 131.8,96.4 131.8,85 133.8,83 133.8,76.55 133.25,76 NTC16.TP
N$78  (1 unrouted)
  Top 0.2: R8.1 134.75,68.45 133.6,69.6 133.6,70.65 133.25,71 SOURCE7.TP
  Bottom 0.2: 133.44,94.75 133.44,94.64 132.2,93.4 132.2,85.2 134.2,83.2 134.2,71.95 133.25,71 SOURCE7.TP
N$79  (1 unrouted)
  Top 0.2: 136,52.25 IC8.CURRENT-2 137.8,54.02 137.8,66.6 134.2,70.2 134.2,75.4 133.8,75.8 133.8,83 131.8,85 131.8,102 132.8,103 133.47,103
  Top 1.27: IC8.CURRENT-2 136,52
  Top 2: IC8.CURRENT-2 IC8.CURRENT-1 DRAIN7.TP
  Bottom 1.27: IC8.CURRENT-2 136,52
  Bottom 2: 136,52 IC8.CURRENT-1 DRAIN7.TP
N$80
  Top 1.27: IC8.CURRENT+1 136,60
  Top 2: COIL7.TP 133,47 133,54 | IC8.CURRENT+1 IC8.CURRENT+2 133,54.3
  Bottom 0.2: 133,54 133,54.3
  Bottom 2: COIL7.TP 133,47 133,54 | IC8.CURRENT+1 IC8.CURRENT+2 133,54.3
N$81
  Bottom 0.2: IC9.+V 154,80.25 156.75,83 156.75,102.15 J9.5
N$82
  Top 0.2: IC9.-V 154,77.75 156.75,80.5 156.75,99.41 J9.4
N$83
  Top 0.2: J9.3 150.8,99 150.2,98.4 150.2,85.2 152.2,83.2 152.2,76 152.6,75.6 152.6,71.4 IC9.OUT
N$84
  Top 0.2: IC9.GND2 IC9.GND1 152.6,76.48 152.6,83.4 150.6,85.4 150.6,91.6 153,94 153,94.84 J9.2
N$85
  Top 0.2: R9.2 152.1,65.3 151.6,65.8 151.6,66.6 151.2,67 GATE8.TP
  Bottom 0.2: J9.1 150.6,89.7 150.6,85.4 152.6,83.4 152.6,68.4 151.2,67 GATE8.TP
N$86
  Bottom 0.2: J9.8 150.87,100.37 149.25,98.75 149.25,80.25 NTC17.TP
N$87
  Bottom 0.2: J9.7 151.03,97.63 149.8,96.4 149.8,85 151.8,83 151.8,76.55 151.25,76 NTC18.TP
N$88  (1 unrouted)
  Top 0.2: R9.1 152.75,68.45 151.6,69.6 151.6,70.65 151.25,71 SOURCE8.TP
  Bottom 0.2: 151.44,94.75 151.44,94.64 150.2,93.4 150.2,85.2 152.2,83.2 152.2,71.95 151.25,71 SOURCE8.TP
N$89  (1 unrouted)
  Top 0.2: 154,52.25 IC9.CURRENT-2 155.8,54.02 155.8,66.6 152.2,70.2 152.2,75.4 151.8,75.8 151.8,83 149.8,85 149.8,102 150.8,103 151.47,103
  Top 1.27: IC9.CURRENT-2 154,52
  Top 2: IC9.CURRENT-2 IC9.CURRENT-1 DRAIN8.TP
  Bottom 1.27: IC9.CURRENT-2 154,52
  Bottom 2: 154,52 IC9.CURRENT-1 DRAIN8.TP
N$90
  Top 0.2: 151,54 151,54.3
  Top 1.27: IC9.CURRENT+1 154,60
  Top 2: COIL8.TP 151,47 151,54 | IC9.CURRENT+1 IC9.CURRENT+2 151,54.3
  Bottom 2: COIL8.TP 151,47 151,54 | IC9.CURRENT+1 IC9.CURRENT+2 151,54.3
N$91
  Bottom 0.2: IC10.+V 172,80.25 174.75,83 174.75,102.15 J10.5
N$92
  Top 0.2: IC10.-V 172,77.75 174.75,80.5 174.75,99.41 J10.4
N$93
  Top 0.2: J10.3 168.8,99 168.2,98.4 168.2,85.2 170.2,83.2 170.2,76 170.6,75.6 170.6,71.4 IC10.OUT
N$94
  Top 0.2: IC10.GND2 IC10.GND1 170.6,76.48 170.6,83.4 168.6,85.4 168.6,91.6 171,94 171,94.84 J10.2
N$95
  Top 0.2: R10.2 170.1,65.3 169.6,65.8 169.6,66.6 169.2,67 GATE9.TP
  Bottom 0.2: J10.1 168.6,89.7 168.6,85.4 170.6,83.4 170.6,68.4 169.2,67 GATE9.TP
N$96
  Bottom 0.2: J10.8 168.87,100.37 167.25,98.75 167.25,80.25 NTC19.TP
N$97
  Bottom 0.2: J10.7 169.03,97.63 167.8,96.4 167.8,85 169.8,83 169.8,76.55 169.25,76 NTC20.TP
N$98  (1 unrouted)
  Top 0.2: R10.1 170.75,68.45 169.6,69.6 169.6,70.65 169.25,71 SOURCE9.TP
  Bottom 0.2: 169.44,94.75 169.44,94.64 168.2,93.4 168.2,85.2 170.2,83.2 170.2,71.95 169.25,71 SOURCE9.TP
N$99  (1 unrouted)
  Top 0.2: 172,52.25 IC10.CURRENT-2 173.8,54.02 173.8,66.6 170.2,70.2 170.2,75.4 169.8,75.8 169.8,83 167.8,85 167.8,102 168.8,103 169.47,103
  Top 1.27: IC10.CURRENT-2 172,52
  Top 2: IC10.CURRENT-2 IC10.CURRENT-1 DRAIN9.TP
  Bottom 1.27: IC10.CURRENT-2 172,52
  Bottom 2: 172,52 IC10.CURRENT-1 DRAIN9.TP
N$100
  Top 0.2: 169,54 169,54.3
  Top 1.27: IC10.CURRENT+1 172,60
  Top 2: COIL9.TP 169,47 169,54 | IC10.CURRENT+1 IC10.CURRENT+2 169,54.3
  Bottom 2: COIL9.TP 169,47 169,54 | IC10.CURRENT+1 IC10.CURRENT+2 169,54.3
N$101
  Bottom 0.2: IC11.+V 190,80.25 192.75,83 192.75,102.15 J11.5
N$102
  Top 0.2: IC11.-V 190,77.75 192.75,80.5 192.75,99.41 J11.4
N$103
  Top 0.2: J11.3 186.8,99 186.2,98.4 186.2,85.2 188.2,83.2 188.2,76 188.6,75.6 188.6,71.4 IC11.OUT
N$104
  Top 0.2: IC11.GND2 IC11.GND1 188.6,76.48 188.6,83.4 186.6,85.4 186.6,91.6 189,94 189,94.84 J11.2
N$105
  Top 0.2: R11.2 188.1,65.3 187.6,65.8 187.6,66.6 187.2,67 GATE10.TP
  Bottom 0.2: J11.1 186.6,89.7 186.6,85.4 188.6,83.4 188.6,68.4 187.2,67 GATE10.TP
N$106
  Bottom 0.2: J11.8 186.87,100.37 185.25,98.75 185.25,80.25 NTC21.TP
N$107
  Bottom 0.2: J11.7 187.03,97.63 185.8,96.4 185.8,85 187.8,83 187.8,76.55 187.25,76 NTC22.TP
N$108  (1 unrouted)
  Top 0.2: R11.1 188.75,68.45 187.6,69.6 187.6,70.65 187.25,71 SOURCE10.TP
  Bottom 0.2: 187.44,94.75 187.44,94.64 186.2,93.4 186.2,85.2 188.2,83.2 188.2,71.95 187.25,71 SOURCE10.TP
N$109  (1 unrouted)
  Top 0.2: 190,52.25 IC11.CURRENT-2 191.8,54.02 191.8,66.6 188.2,70.2 188.2,75.4 187.8,75.8 187.8,83 185.8,85 185.8,102 186.8,103 187.47,103
  Top 1.27: IC11.CURRENT-2 190,52
  Top 2: IC11.CURRENT-2 IC11.CURRENT-1 DRAIN10.TP
  Bottom 1.27: IC11.CURRENT-2 190,52
  Bottom 2: 190,52 IC11.CURRENT-1 DRAIN10.TP
N$110
  Top 0.2: 187,54 187,54.3
  Top 1.27: IC11.CURRENT+1 190,60
  Top 2: 187,54 187,47 COIL10.TP | IC11.CURRENT+1 IC11.CURRENT+2 187,54.3
  Bottom 2: COIL10.TP 187,47 187,54 | IC11.CURRENT+1 IC11.CURRENT+2 187,54.3
N$111
  Bottom 0.2: 0,2 0,0 2,0
N$112
  Top 0.2: 0,2 0,0 2,0
N$113
  Top 0.2: 194,120 196,120 196,118
N$114
  Bottom 0.2: 194,120 196,120 196,118
N$115
  Bottom 0.2: 194,0 196,0 196,2
N$116
  Top 0.2: 196,2 196,0 194,0
N$117
  Top 0.2: 2,120 0,120 0,118
N$118
  Bottom 0.2: 0,118 0,120 2,120

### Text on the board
Top: Ch1 | Ch2 | Ch3 | Ch4 | Ch5 | Ch6 | Ch7 | Ch8 | Ch9 | Ch10 | Ch11 | Therm | Therm | Therm | Therm | Therm | Therm | Therm | Therm | Therm | Therm | Therm | S | Src | Src | Src | Src | Src | Src | Src | Src | Src | Src | G | Gat | Gat | Gat | Gat | Gat | Gat | Gat | Gat | Gat | Gat | Coil | Drain | Coil | Drain | Coil | Drain | Coil | Drain | Coil | Drain | Coil | Drain | Coil | Drain | Coil | Drain | Coil | Drain | Coil | Drain | Coil | Drain | "Shimmer" Shim Coils, Rev:A | University of Toronto - Physics | J. Thywissen Labs
Document: "Shimmer" Shim Coils | Wish List for Rev:B | J. Thywissen Labs | - Move DB9 2mm further from sensor (barely fits). | A. Stummer, May 2010 | A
